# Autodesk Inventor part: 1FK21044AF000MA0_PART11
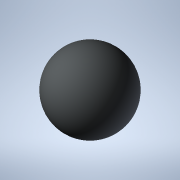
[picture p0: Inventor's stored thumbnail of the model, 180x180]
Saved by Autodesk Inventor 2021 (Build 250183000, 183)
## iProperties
Created: 2025-04
Part Number: 1FK21044AF000MA0_PART11
Material: Generic
Catalog Web Link: www.3dfindit.com
Description: -Servo synchronous motor
Document SubType Name: Modeling
Designer: psAdmin
Mass: 0.137258 g
Surface Area: 1.2868 cm^2
Volume: 0.137258 cm^3
Density: 1 g/cm^3
Appearance: PSOLRGB-212-217-219
Category: PARTsolutions
Title: 1FK21044AF000MA0_PART11
Author: Cadenas PARTsolutions
Comments: Servo synchronous motor
Sending System: PARTsolutions
Preprocessor: ST-DEVELOPER v19.3
PSOL_IDENT_0: {$CADENAS_DATA/23d-libs/siemens_ag/_cat_/39/c4/1fk21044af000ma0.prj},216 {VTYP=3D},{NB=1FK21044AF000
PSOL_IDENT_1: MA0_PART11},{LINA=1FK21044AF000MA0_PART11},{NN=1FK21044AF000MA0_PART11},{NOPRJ=TRUE},{DATE=19.08.202
PSOL_IDENT_2: 5 14:00:33},{GEOMDATE=30.07.2025 02:02:22},{VERSION=},{LINEID=10},{WBVAR=},{WBNUMERIC=}  {NB=1FK2104
PSOL_IDENT_3: 4AF000MA0_PART11},{LINA=1FK21044AF000MA0_PART11},{KT=DUMMY},{PREVIEW=../../../_pool_/cb/72/p_d211_xx
PSOL_IDENT_4: _00434j.png},{DESCSHORT=SIMOTICS S-1FK2 HD, SINAMICS S210 3AC 400V-480V, 1.27 Nm, 3000 rpm},{DESCLON
PSOL_IDENT_5: G=SIMOTICS S-1FK2 HD servo motor M0=1.27 Nm; PN = 0.4 kW at nN=3000 rpm (380-480 V); PN = 0.2 kW at
PSOL_IDENT_6: nN=1500 rpm (200-240 V); degree of protection IP64; cylindrical shaft D19x40mm; absolute encoder 22-
PSOL_IDENT_7: bit + 12-bit multiturn (encoder AM22DQC); with OCC interface; plug size M17, rotatable; SIMOTICS S-1
PSOL_IDENT_8: FK2 servomotorfor a wide range of uses in industrial environments. SIMOTICS S‑1FK2 servomotors are c
PSOL_IDENT_9: ompact synchronous motors with a high dynamic performance that set themselves apart as a result of t
PSOL_IDENT_10: heir high power density, degree of protection and overload capability. The motors are available in t
PSOL_IDENT_11: wo variants: as High Dynamic variant (highest dynamic performance as a result of the low intrinsic m
PSOL_IDENT_12: oment of inertia for applications demanding a high dynamic performance with low moved masses) - and
PSOL_IDENT_13: as Compact variant (precise and stable closed-loop control for medium up to large moved masses as a
PSOL_IDENT_14: result of a medium intrinsic moment of inertia). SIMOTICSS‑1FK2 servomotors fully exploit their stre
PSOL_IDENT_15: ngths in a system with the SINAMICSS210 frequency converter and simple connection using the one cabl
PSOL_IDENT_16: e connection (OCC). Advantages include the short control and positioning times, fast and precise cor
PSOL_IDENT_17: rection of disturbing quantities as well as stable control with a high dynamic performance. The serv
PSOL_IDENT_18: o motors can be configured to address a wide range of requirements. For example with and without hol
PSOL_IDENT_19: ding brake, IP64 or IP65 degree of protection, singleturn or multiturn absolute encoders - to name j
PSOL_IDENT_20: ust a few. Further, the servomotors are available in different shaft heights extending from 20 to 10
PSOL_IDENT_21: 0. A shaft sealing ring is available to achieve an IP65 degree of protection and for subsequent moun
PSOL_IDENT_22: ting at the motor or as spare part. SIMOTICS - the optimum motor for each and every motion control a
PSOL_IDENT_23: pplication.},{INTNO=804766906428},{SUPPLIERALTNO=1FK2104-4AF00-0MA0},{MANUID=1FK21044AF000MA0},{MANU
PSOL_IDENT_24: NAME=Siemens},{MANUTYPEDESC=Synchronous motor 1FK2-HD 1.27 NM},{AAU732=SIMOTICS},{AAO057=S-1FK2},{AA
PSOL_IDENT_25: U734=SIMOTICS S-1FK2 HD servo motor M0=1.27 Nm; PN = 0.4 kW at nN=3000 rpm (380-480 V); PN = 0.2 kW
PSOL_IDENT_26: at nN=1500 rpm (200-240 V); degree of protection IP64; cylindrical shaft D19x40mm; absolute encoder
PSOL_IDENT_27: 22-bit + 12-bit multiturn (encoder AM22DQC); with OCC interface; plug size M17, rotatable;},{AAW338=
PSOL_IDENT_28: Synchronous motor 1FK2-HD 1.27 NM},{AAO742=SIMOTICS},{AAO663=4042948693322},{NOCUPEROU=1},{PRICEQUAN
PSOL_IDENT_29: TITY=1},{QUANTITYMIN=1},{QUANTITYINT=1},{CTN=85015100},{COO=DE},{AAO676=1FK2104-4AF00-0MA0},{AAO677=
PSOL_IDENT_30: Siemens AG},{ORDERUNIT=C62},{CONTENTUNIT=C62}
NB: 1FK21044AF000MA0_PART11
NT: Servo synchronous motor
NBSYN: $MANUID._PART11
LINA: 1FK21044AF000MA0_PART11
CATALOG: SIEMENS
PREVIEW: ../../../_pool_/cb/72/p_d211_xx_00434j.png
DESCSHORT: SIMOTICS S-1FK2 HD, SINAMICS S210 3AC 400V-480V, 1.27 Nm, 3000 rpm
DESCLONG: SIMOTICS S-1FK2 HD servo motor M0=1.27 Nm; PN = 0.4 kW at nN=3000 rpm (380-480 V); PN = 0.2 kW at nN=1500 rpm (200-240 V); degree of protection IP64; cylindrica
INTNO: 804766906428
SUPPLIERALTNO: 1FK2104-4AF00-0MA0
MANUID: 1FK21044AF000MA0
MANUNAME: Siemens
MANUTYPEDESC: Synchronous motor 1FK2-HD 1.27 NM
AAU732: SIMOTICS
AAO057: S-1FK2
AAU734: SIMOTICS S-1FK2 HD servo motor M0=1.27 Nm; PN = 0.4 kW at nN=3000 rpm (380-480 V); PN = 0.2 kW at nN=1500 rpm (200-240 V); degree of protection IP64; cylindrica
AAW338: Synchronous motor 1FK2-HD 1.27 NM
AAO742: SIMOTICS
AAO663: 4042948693322.0
NOCUPEROU: 1
PRICEQUANTITY: 1
QUANTITYMIN: 1
QUANTITYINT: 1
CTN: 85015100
COO: DE
ARTICLENO: 1FK21044AF000MA0_PART11
BOMINFO: 1FK21044AF000MA0_PART11
CREATOR: CADENAS GmbH
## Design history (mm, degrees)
feature "2025_04_17_15_01_28_0038"
body "Solid1"
